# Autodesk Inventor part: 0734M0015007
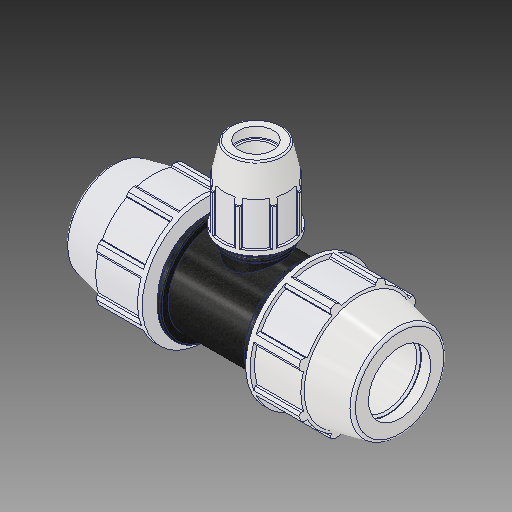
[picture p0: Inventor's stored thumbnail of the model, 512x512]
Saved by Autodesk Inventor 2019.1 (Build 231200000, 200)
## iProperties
Created: 2017-02
Part Number: 0734M0015007
Material: PVC-Piping
Description: PLASSON REDUCING TEE 1 1/2'' - 3/4'' - 1 1/2''
Document SubType Name: Modeling
Designer: KIM
Mass: 92.6774 g
Surface Area: 199.44 cm^2
Volume: 66.1981 cm^3
Density: 1.4 g/cm^3
Appearance: PTFE
Author: Кирилл
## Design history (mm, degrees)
derived "0734M0.ipt"
feature "Solid1::0734M0.ipt"
feature "Solid2::0734M0.ipt"
tag "TaggingFeature1"
body "Solid1"
other parameters: "d2" = 48.1, "d4" = 9.24983, "d5" = 31.07944, "d7" = 96.012, "d11" = 3.69993, "d13" = 120 deg, "d14" = 72.15, "d15" = 12 deg, "d16" = 83.53044, "d18" = 2.405, "d19" = 35 deg, "d20" = 17.5 deg, "d21" = 89.29116, "d23" = 0, "d25" = 360 deg, "d27" = 1.92024, "d33" = 0.962, "d42" = 39.95928, "d43" = 2.88036, "d46" = 1.443, "d67" = 72.009, "d76" = 26.6, "d77" = 53.086, "d78" = 12 deg, "d79" = 106.934, "d80" = 120 deg, "d81" = 39.9, "d82" = 8.91117, "d87" = 3.56447, "d89" = 26.7335, "d90" = 32.0802, "d96" = 18.49967, "d98" = 49.36998, "d99" = 35 deg, "d100" = 17.5 deg, "d102" = 0, "d103" = 1.06172, "d107" = 360 deg, "d109" = 0.798, "d112" = 1.33, "d113" = 3.53907, "d114" = 0, "d117" = 221.996, "d118" = 46.18482, "d126" = 43.29, "d127" = 92.964, "d131" = 4.27736, "d132" = 23.94, "d133" = 77.978, "d135" = 0, "d138" = 4.43992, "d143" = 0, "d148" = 39.8145, "d168" = 43.29, "d170" = 0, "d171" = 26.6, "d173" = 0, "d176" = 3.53907, "d177" = 0, "d_" = 48.1, "E_" = 96.012, "A_" = 106.934, "l_" = 92.964, "E_1" = 53.086, "l_1" = 77.978, "d_1" = 26.6, "H_" = 221.996
